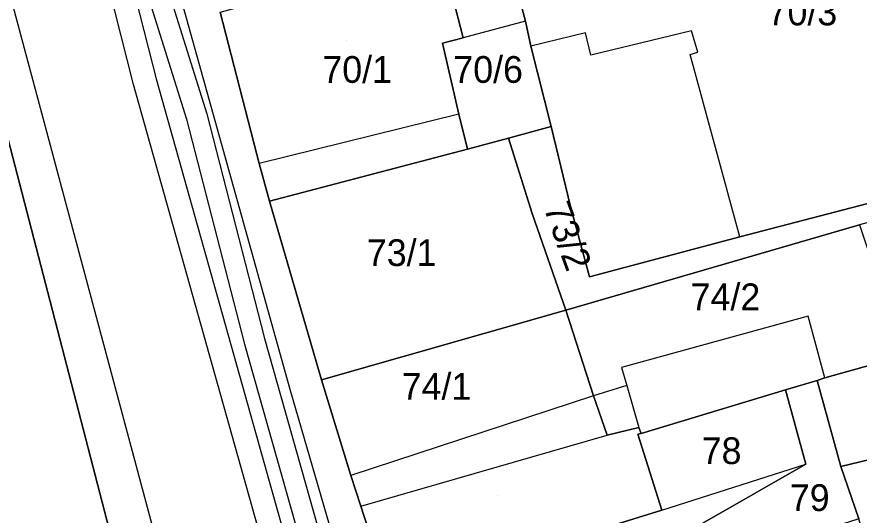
# Model space of a CAD drawing. Extents: x -263423 to -261326, y -1240067 to -1237864.
# Drawn here: x -262980.7 to -262917.7, y -1239503 to -1239465.8 of the extents above; entities that cross this region are included whole.
import ezdxf

# ---------------------------------------------------------------- set-up
doc = ezdxf.new("R2010")
doc.units = 0
for name, color, linetype in [('body_kn', 7, 'Continuous'), ('kladpar_druhypozemkov', 7, 'Continuous'), ('kladpar_hranice', 7, 'Continuous'), ('kladpar_parcelnecisla', 7, 'Continuous'), ('kladpar_plochy', 7, 'Continuous'), ('tarchy_linie', 7, 'Continuous'), ('zappar_hrandruhpozemk', 7, 'Continuous')]:
    doc.layers.add(name, color=color, linetype=linetype)

msp = doc.modelspace()

# ---------------------------------------------------------------- linework, layer by layer
at = {"layer": 'body_kn'}
for p, q in [((-262942.68, -1239466.11), (-262942.68, -1239466.11)), ((-262942.68, -1239466.11), (-262942.68, -1239466.11)), ((-262938.19, -1239466.97), (-262938.19, -1239466.97)), ((-262930.26, -1239466.82), (-262930.26, -1239466.82)), ((-262947.34, -1239467.34), (-262947.34, -1239467.34)), ((-262948.87, -1239467.75), (-262948.87, -1239467.75)), ((-262942.28, -1239467.96), (-262942.28, -1239467.96)), ((-262937.79, -1239468.63), (-262937.79, -1239468.63)), ((-262930.36, -1239468.6), (-262930.36, -1239468.6)), ((-262929.79, -1239468.42), (-262929.79, -1239468.42)), ((-262970.3, -1239470.42), (-262970.3, -1239470.42)), ((-262971.98, -1239470.84), (-262971.98, -1239470.84)), ((-262966.51, -1239473.04), (-262966.51, -1239473.04)), ((-262947.65, -1239473.05), (-262947.65, -1239473.05)), ((-262947.65, -1239473.05), (-262947.65, -1239473.05)), ((-262968.01, -1239473.43), (-262968.01, -1239473.43)), ((-262940.76, -1239473.97), (-262940.76, -1239473.97)), ((-262943.95, -1239474.85), (-262943.95, -1239474.85)), ((-262947.01, -1239475.67), (-262947.01, -1239475.67)), ((-262947.01, -1239475.67), (-262947.01, -1239475.67)), ((-262962.58, -1239476.73), (-262962.58, -1239476.73)), ((-262961.82, -1239479.55), (-262961.82, -1239479.55)), ((-262939.3, -1239479.97), (-262939.3, -1239479.97)), ((-262939.3, -1239479.97), (-262939.3, -1239479.97)), ((-262942.17, -1239480.48), (-262942.17, -1239480.48)), ((-262926.66, -1239482.22), (-262926.66, -1239482.22)), ((-262926.66, -1239482.22), (-262926.66, -1239482.22)), ((-262937.9, -1239485.21), (-262937.9, -1239485.21)), ((-262939.66, -1239487.72), (-262939.66, -1239487.72)), ((-262939.66, -1239487.72), (-262939.66, -1239487.72)), ((-262921.53, -1239488.17), (-262921.53, -1239488.17)), ((-262963.69, -1239490.26), (-262963.69, -1239490.26)), ((-262962.2, -1239489.84), (-262962.2, -1239489.84)), ((-262935.51, -1239492), (-262935.51, -1239492)), ((-262920.29, -1239492.78), (-262920.29, -1239492.78)), ((-262920.29, -1239492.78), (-262920.29, -1239492.78)), ((-262957.93, -1239492.91), (-262957.93, -1239492.91)), ((-262935.09, -1239493.34), (-262935.09, -1239493.34)), ((-262935.09, -1239493.34), (-262935.09, -1239493.34)), ((-262920.87, -1239492.96), (-262920.87, -1239492.96)), ((-262960.29, -1239493.62), (-262960.29, -1239493.62)), ((-262960.29, -1239493.62), (-262960.29, -1239493.62)), ((-262923.23, -1239493.67), (-262923.23, -1239493.67)), ((-262923.23, -1239493.67), (-262923.23, -1239493.67)), ((-262937.58, -1239494.12), (-262937.58, -1239494.12)), ((-262937.58, -1239494.12), (-262937.58, -1239494.12)), ((-262934.21, -1239496.48), (-262934.21, -1239496.48)), ((-262936.57, -1239497.06), (-262936.57, -1239497.06)), ((-262934.28, -1239496.98), (-262934.28, -1239496.98)), ((-262934.03, -1239496.93), (-262934.03, -1239496.93)), ((-262921.71, -1239499.23), (-262921.71, -1239499.23)), ((-262921.71, -1239499.23), (-262921.71, -1239499.23)), ((-262919.11, -1239499.41), (-262919.11, -1239499.41)), ((-262955.74, -1239500.08), (-262955.74, -1239500.08)), ((-262954.99, -1239502.36), (-262954.99, -1239502.36)), ((-262954.99, -1239502.36), (-262954.99, -1239502.36)), ((-262932.49, -1239502.67), (-262932.49, -1239502.67)), ((-262932.49, -1239502.67), (-262932.49, -1239502.67))]:
    msp.add_line(p, q, dxfattribs=at)
at = {"layer": 'kladpar_druhypozemkov'}
for p, q in [((-262956.06, -1239467.51), (-262956.06, -1239467.51)), ((-262944.15, -1239468.82), (-262944.15, -1239468.82)), ((-262941.36, -1239480.21), (-262941.36, -1239480.21)), ((-262952.16, -1239482.01), (-262952.16, -1239482.01)), ((-262926.59, -1239485.93), (-262926.59, -1239485.93)), ((-262949.36, -1239492.31), (-262949.36, -1239492.31)), ((-262927.77, -1239497.13), (-262927.77, -1239497.13)), ((-262921.37, -1239500.63), (-262921.37, -1239500.63)), ((-262944.79, -1239501.56), (-262944.79, -1239501.56))]:
    msp.add_line(p, q, dxfattribs=at)
at = {"layer": 'kladpar_hranice'}
for points in [[(-262944.38, -1239459.78), (-262942.68, -1239466.11), (-262942.28, -1239467.96), (-262940.76, -1239473.97), (-262943.95, -1239474.85), (-262947.01, -1239475.67), (-262947.65, -1239473.05), (-262948.87, -1239467.75), (-262947.34, -1239467.34), (-262948.98, -1239460.95), (-262944.38, -1239459.78)], [(-262894.74, -1239461.88), (-262893.33, -1239467.12), (-262892.44, -1239469.62), (-262891.46, -1239474.21), (-262900.78, -1239477), (-262910.1, -1239479.27), (-262910.28, -1239478.7), (-262915.13, -1239479.99), (-262915.37, -1239479.29), (-262926.66, -1239482.22), (-262937.9, -1239485.21), (-262939.3, -1239479.97), (-262940.76, -1239473.97), (-262942.28, -1239467.96), (-262942.68, -1239466.11), (-262944.38, -1239459.78)], [(-262948.98, -1239460.95), (-262947.34, -1239467.34), (-262948.87, -1239467.75), (-262947.65, -1239473.05), (-262947.01, -1239475.67), (-262961.82, -1239479.55), (-262962.58, -1239476.73), (-262965.51, -1239465.42), (-262948.98, -1239460.95)], [(-262935.95, -1239581.4), (-262939.79, -1239570.1), (-262940.62, -1239567.74), (-262946.11, -1239551.91), (-262946.36, -1239551.08), (-262946.87, -1239550.44), (-262947.38, -1239549.93), (-262948.08, -1239549.67), (-262953.28, -1239541.87), (-262954.35, -1239537.98), (-262955.69, -1239538.35), (-262964.64, -1239525.12), (-262966.02, -1239520.78), (-262966.85, -1239521.03), (-262967.56, -1239521.21), (-262969.22, -1239521.78), (-262984.05, -1239464.66)], [(-262984.05, -1239464.66), (-262969.22, -1239521.78)], [(-262965.51, -1239465.42), (-262962.58, -1239476.73), (-262961.82, -1239479.55), (-262957.93, -1239492.91), (-262955.74, -1239500.08), (-262954.99, -1239502.36), (-262952.85, -1239509), (-262951.27, -1239514.04), (-262950.07, -1239517.61), (-262948.43, -1239523.23), (-262945.27, -1239531.91), (-262943.25, -1239535.42), (-262940.1, -1239547.61), (-262937.39, -1239556.8), (-262936.63, -1239559.6), (-262933.04, -1239569.94), (-262932.09, -1239572.75), (-262928.43, -1239583.67)], [(-262939.3, -1239479.97), (-262937.9, -1239485.21), (-262926.66, -1239482.22), (-262915.37, -1239479.29), (-262915.13, -1239479.99), (-262910.28, -1239478.7), (-262910.1, -1239479.27), (-262917.7, -1239481.33), (-262939.66, -1239487.72), (-262942.17, -1239480.48), (-262943.95, -1239474.85), (-262940.76, -1239473.97), (-262939.3, -1239479.97)], [(-262947.01, -1239475.67), (-262943.95, -1239474.85), (-262942.17, -1239480.48), (-262939.66, -1239487.72), (-262957.93, -1239492.91), (-262961.82, -1239479.55), (-262947.01, -1239475.67)], [(-262917.7, -1239481.33), (-262914.42, -1239491.13), (-262920.29, -1239492.78), (-262920.87, -1239492.96), (-262923.23, -1239493.67), (-262934.03, -1239496.93), (-262934.21, -1239496.48), (-262936.57, -1239497.06), (-262937.58, -1239494.12), (-262939.66, -1239487.72), (-262917.7, -1239481.33)], [(-262939.66, -1239487.72), (-262937.58, -1239494.12), (-262936.57, -1239497.06), (-262934.21, -1239496.48), (-262934.03, -1239496.93), (-262934.28, -1239496.98), (-262932.49, -1239502.67), (-262944.61, -1239506.43), (-262952.85, -1239509), (-262954.99, -1239502.36), (-262955.74, -1239500.08), (-262957.93, -1239492.91), (-262939.66, -1239487.72)], [(-262914.42, -1239491.13), (-262907.65, -1239489.24), (-262906.75, -1239494.15), (-262906.29, -1239496.32), (-262919.11, -1239499.41), (-262920.87, -1239492.96), (-262920.29, -1239492.78), (-262914.42, -1239491.13)], [(-262921.71, -1239499.23), (-262923.23, -1239493.67), (-262920.87, -1239492.96), (-262919.11, -1239499.41), (-262917.76, -1239503.32), (-262930.91, -1239507.52), (-262943.17, -1239511.53), (-262933.07, -1239505.72), (-262921.71, -1239499.23)], [(-262923.23, -1239493.67), (-262921.71, -1239499.23), (-262933.07, -1239505.72), (-262943.17, -1239511.53), (-262951.27, -1239514.04), (-262952.85, -1239509), (-262944.61, -1239506.43), (-262932.49, -1239502.67), (-262934.28, -1239496.98), (-262934.03, -1239496.93), (-262923.23, -1239493.67)], [(-262906.29, -1239496.32), (-262904.62, -1239501.16), (-262901.82, -1239500.28), (-262900.81, -1239503.15), (-262897.42, -1239502.22), (-262895.72, -1239508.28), (-262899.36, -1239509.34), (-262901.98, -1239510.16), (-262903.68, -1239504.29), (-262916.5, -1239507.47), (-262917.76, -1239503.32), (-262919.11, -1239499.41), (-262906.29, -1239496.32)]]:
    msp.add_lwpolyline(points, dxfattribs=at)
at = {"layer": 'kladpar_plochy'}
for points in [[(-262944.38, -1239459.78), (-262942.68, -1239466.11), (-262942.28, -1239467.96), (-262940.76, -1239473.97), (-262943.95, -1239474.85), (-262947.01, -1239475.67), (-262947.65, -1239473.05), (-262948.87, -1239467.75), (-262947.34, -1239467.34), (-262948.98, -1239460.95)], [(-262948.98, -1239460.95), (-262947.34, -1239467.34), (-262948.87, -1239467.75), (-262947.65, -1239473.05), (-262947.01, -1239475.67), (-262961.82, -1239479.55), (-262962.58, -1239476.73), (-262965.51, -1239465.42)], [(-262939.3, -1239479.97), (-262937.9, -1239485.21), (-262926.66, -1239482.22), (-262915.37, -1239479.29), (-262915.13, -1239479.99), (-262910.28, -1239478.7), (-262910.1, -1239479.27), (-262917.7, -1239481.33), (-262939.66, -1239487.72), (-262942.17, -1239480.48), (-262943.95, -1239474.85), (-262940.76, -1239473.97)], [(-262947.01, -1239475.67), (-262943.95, -1239474.85), (-262942.17, -1239480.48), (-262939.66, -1239487.72), (-262957.93, -1239492.91), (-262961.82, -1239479.55)], [(-262917.7, -1239481.33), (-262914.42, -1239491.13), (-262920.29, -1239492.78), (-262920.87, -1239492.96), (-262923.23, -1239493.67), (-262934.03, -1239496.93), (-262934.21, -1239496.48), (-262936.57, -1239497.06), (-262937.58, -1239494.12), (-262939.66, -1239487.72)], [(-262939.66, -1239487.72), (-262937.58, -1239494.12), (-262936.57, -1239497.06), (-262934.21, -1239496.48), (-262934.03, -1239496.93), (-262934.28, -1239496.98), (-262932.49, -1239502.67), (-262944.61, -1239506.43), (-262952.85, -1239509), (-262954.99, -1239502.36), (-262955.74, -1239500.08), (-262957.93, -1239492.91)], [(-262914.42, -1239491.13), (-262907.65, -1239489.24), (-262906.75, -1239494.15), (-262906.29, -1239496.32), (-262919.11, -1239499.41), (-262920.87, -1239492.96), (-262920.29, -1239492.78)], [(-262921.71, -1239499.23), (-262923.23, -1239493.67), (-262920.87, -1239492.96), (-262919.11, -1239499.41), (-262917.76, -1239503.32), (-262930.91, -1239507.52), (-262943.17, -1239511.53), (-262933.07, -1239505.72)], [(-262923.23, -1239493.67), (-262921.71, -1239499.23), (-262933.07, -1239505.72), (-262943.17, -1239511.53), (-262951.27, -1239514.04), (-262952.85, -1239509), (-262944.61, -1239506.43), (-262932.49, -1239502.67), (-262934.28, -1239496.98), (-262934.03, -1239496.93)], [(-262906.29, -1239496.32), (-262904.62, -1239501.16), (-262901.82, -1239500.28), (-262900.81, -1239503.15), (-262897.42, -1239502.22), (-262895.72, -1239508.28), (-262899.36, -1239509.34), (-262901.98, -1239510.16), (-262903.68, -1239504.29), (-262916.5, -1239507.47), (-262917.76, -1239503.32), (-262919.11, -1239499.41)]]:
    msp.add_lwpolyline(points, close=True, dxfattribs=at)
for points in [[(-262894.74, -1239461.88), (-262893.33, -1239467.12), (-262892.44, -1239469.62), (-262891.46, -1239474.21), (-262900.78, -1239477), (-262910.1, -1239479.27), (-262910.28, -1239478.7), (-262915.13, -1239479.99), (-262915.37, -1239479.29), (-262926.66, -1239482.22), (-262937.9, -1239485.21), (-262939.3, -1239479.97), (-262940.76, -1239473.97), (-262942.28, -1239467.96), (-262942.68, -1239466.11), (-262944.38, -1239459.78)], [(-262984.05, -1239464.66), (-262969.22, -1239521.78), (-262975.98, -1239523.72), (-262984.61, -1239516.59)], [(-262935.95, -1239581.4), (-262939.79, -1239570.1), (-262940.62, -1239567.74), (-262946.11, -1239551.91), (-262946.36, -1239551.08), (-262946.87, -1239550.44), (-262947.38, -1239549.93), (-262948.08, -1239549.67), (-262953.28, -1239541.87), (-262954.35, -1239537.98), (-262955.69, -1239538.35), (-262964.64, -1239525.12), (-262966.02, -1239520.78), (-262966.85, -1239521.03), (-262967.56, -1239521.21), (-262969.22, -1239521.78), (-262984.05, -1239464.66)], [(-262965.51, -1239465.42), (-262962.58, -1239476.73), (-262961.82, -1239479.55), (-262957.93, -1239492.91), (-262955.74, -1239500.08), (-262954.99, -1239502.36), (-262952.85, -1239509), (-262951.27, -1239514.04), (-262950.07, -1239517.61), (-262948.43, -1239523.23), (-262945.27, -1239531.91), (-262943.25, -1239535.42), (-262940.1, -1239547.61), (-262937.39, -1239556.8), (-262936.63, -1239559.6), (-262933.04, -1239569.94), (-262932.09, -1239572.75), (-262928.43, -1239583.67)]]:
    msp.add_lwpolyline(points, dxfattribs=at)
at = {"layer": 'tarchy_linie'}
for points in [[(-263003.83, -1239347.76), (-262995.31, -1239379.36), (-262983.91, -1239420.46), (-262973.03, -1239459.64), (-262970.3, -1239470.42), (-262956.01, -1239521.26), (-262948.98, -1239533.43)], [(-262997.74, -1239368.62), (-262983.51, -1239418.62), (-262972.9, -1239457.82), (-262968.01, -1239473.43), (-262963.69, -1239490.26), (-262951.28, -1239534.16)], [(-262996.25, -1239368.2), (-262982.01, -1239418.22), (-262971.42, -1239457.36), (-262966.51, -1239473.04), (-262962.2, -1239489.84), (-262952.7, -1239523.45), (-262946.54, -1239534.09), (-262945.44, -1239533.99), (-262944.48, -1239536.54), (-262941.68, -1239544.05), (-262937.39, -1239556.8), (-262936.63, -1239559.6), (-262933.04, -1239569.94), (-262932.09, -1239572.75), (-262928.43, -1239583.67)], [(-262935.07, -1239581.22), (-262946.48, -1239547.32), (-262943.87, -1239546.62), (-262944.3, -1239545.03), (-262944.73, -1239543.44), (-262944.88, -1239543.48), (-262947.59, -1239544.21), (-262949.46, -1239539.22), (-262952.28, -1239540.05), (-262952.77, -1239538.58), (-262952.85, -1239538.33), (-262950.4, -1239537.55), (-262947.53, -1239536.64), (-262948.06, -1239534.97), (-262948.59, -1239533.3), (-262948.96, -1239533.42), (-262951.28, -1239534.16), (-262952.76, -1239534.63), (-262955.13, -1239526.23), (-262957.62, -1239521.94), (-262971.98, -1239470.84), (-262974.3, -1239461.67), (-263002.42, -1239467.19)]]:
    msp.add_lwpolyline(points, dxfattribs=at)
at = {"layer": 'zappar_hrandruhpozemk'}
for p, q in [((-262970.58, -1239456.73), (-262960.29, -1239493.62)), ((-262966.02, -1239520.78), (-262981.33, -1239463.68)), ((-262942.68, -1239466.11), (-262947.34, -1239467.34)), ((-262926.66, -1239482.22), (-262930.36, -1239468.6)), ((-262947.65, -1239473.05), (-262962.58, -1239476.73)), ((-262921.53, -1239488.17), (-262935.51, -1239492)), ((-262920.29, -1239492.78), (-262921.53, -1239488.17)), ((-262935.09, -1239493.34), (-262937.58, -1239494.12)), ((-262960.29, -1239493.62), (-262952, -1239522.19)), ((-262937.58, -1239494.12), (-262955.74, -1239500.08)), ((-262954.99, -1239502.36), (-262936.57, -1239497.06)), ((-262932.49, -1239502.67), (-262921.71, -1239499.23))]:
    msp.add_line(p, q, dxfattribs=at)
for points in [[(-262930.36, -1239468.6), (-262929.79, -1239468.42), (-262930.26, -1239466.82), (-262937.79, -1239468.63), (-262938.19, -1239466.97), (-262942.28, -1239467.96)], [(-262935.51, -1239492), (-262935.09, -1239493.34), (-262934.21, -1239496.48)]]:
    msp.add_lwpolyline(points, dxfattribs=at)

# ---------------------------------------------------------------- texts
at = {"layer": 'kladpar_parcelnecisla'}
for s, p in [('70/3', (-262924.575, -1239466.41)), ('70/1', (-262957.863, -1239470.71)), ('70/6', (-262948.072, -1239470.71)), ('73/1', (-262954.534, -1239484.41)), ('74/2', (-262930.327, -1239487.71)), ('74/1', (-262951.931, -1239494.41)), ('78', (-262929.504, -1239499.22)), ('79', (-262922.911, -1239502.73))]:
    msp.add_text(s, height=2, dxfattribs=at).set_placement(p)
msp.add_text('73/2', height=2, rotation=290, dxfattribs=at).set_placement((-262941.342, -1239480.045))

doc.saveas('drawing.dxf')
